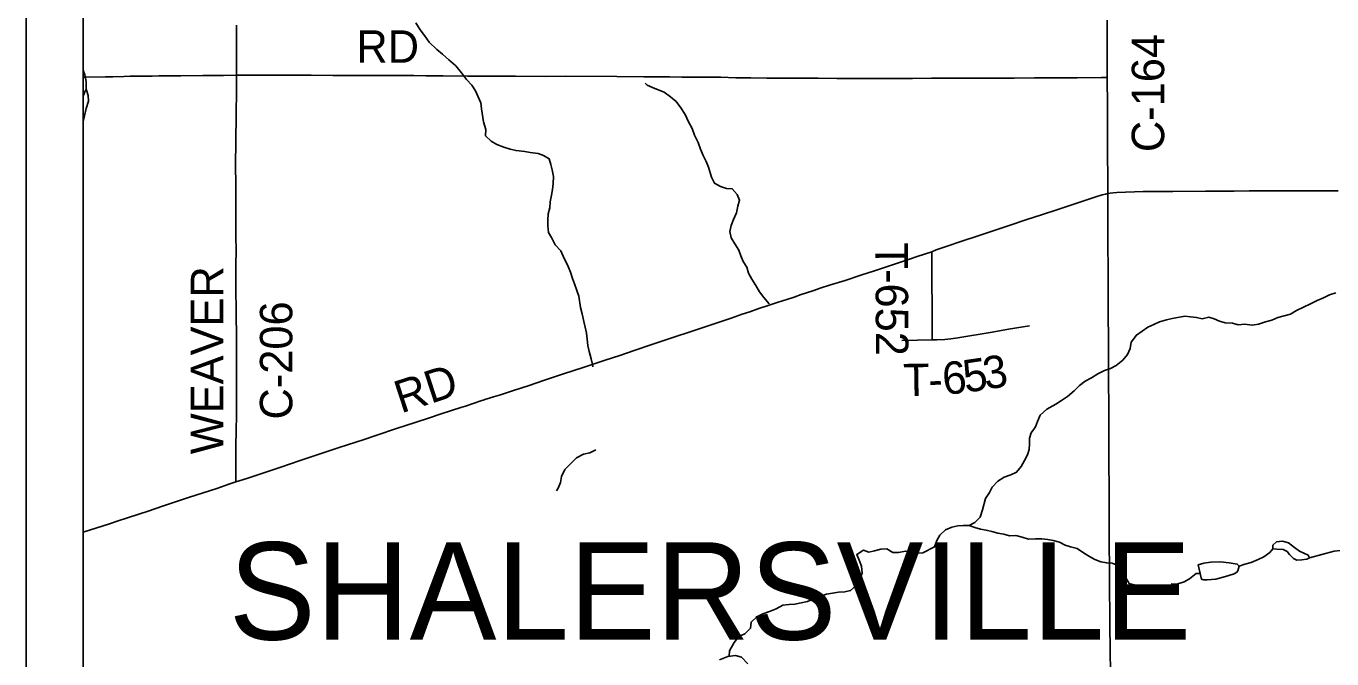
# Model space of a CAD drawing. Extents: x 0 to 34, y 0 to 22.
# Drawn here: x 13.344 to 15.63, y 16.128 to 17.236 of the extents above; entities that cross this region are included whole.
import ezdxf

# ---------------------------------------------------------------- set-up
doc = ezdxf.new("R2010")
doc.units = 0
for name, color, linetype in [('GM_X_Corporation', 7, 'Continuous'), ('GM_X_County_Road', 7, 'Continuous'), ('GM_X_County_Road_Text', 7, 'Continuous'), ('GM_X_Minor_Lake', 7, 'Continuous'), ('GM_X_Minor_River', 7, 'Continuous'), ('GM_X_Township_Road', 7, 'Continuous'), ('GM_X_Township_Road_Text', 7, 'Continuous'), ('GM_X_Township_Text', 7, 'Continuous'), ('SH_Data', 7, 'Continuous')]:
    doc.layers.add(name, color=color, linetype=linetype)

msp = doc.modelspace()

# ---------------------------------------------------------------- linework, layer by layer
at = {"layer": 'GM_X_Corporation'}
msp.add_lwpolyline([(13.4438, 19.9239), (13.4438, 15.6034)], dxfattribs=at)
at = {"layer": 'GM_X_County_Road'}
for points in [[(15.2371, 17.146), (15.2369, 17.1831), (15.2368, 17.2268), (15.2367, 17.2467)], [(13.7121, 17.1501), (13.7121, 17.1537), (13.7121, 17.1637), (13.7123, 17.1947), (13.7125, 17.2376)], [(13.7108, 16.4376), (13.7109, 16.4494), (13.7113, 16.4985), (13.7119, 16.5295), (13.712, 16.5531), (13.7121, 16.5867), (13.7122, 16.6003), (13.7122, 16.6432), (13.7123, 16.6693), (13.7121, 16.6911), (13.7118, 16.7327), (13.7117, 16.7427), (13.7113, 16.7706), (13.7111, 16.7861), (13.7111, 16.814), (13.7116, 16.8469), (13.7113, 16.8636), (13.7113, 16.8841), (13.7113, 16.9021), (13.711, 16.9208), (13.7108, 16.9413), (13.7108, 16.9674), (13.7106, 16.9829), (13.7103, 16.9985), (13.7108, 17.0283), (13.711, 17.0345), (13.7113, 17.0457), (13.7116, 17.0687), (13.7118, 17.0823), (13.7124, 17.1221), (13.7124, 17.1277), (13.7122, 17.1488), (13.7121, 17.1501)], [(15.238, 16.9428), (15.2378, 16.9671), (15.2376, 17.0151), (15.2375, 17.0511), (15.2372, 17.1087), (15.2371, 17.1324), (15.2371, 17.146)], [(15.238, 16.9428), (15.2422, 16.9436), (15.2476, 16.9443), (15.254, 16.9448), (15.2996, 16.9462), (15.3281, 16.9464), (15.3518, 16.9465), (15.409, 16.9467), (15.4593, 16.9472), (15.4854, 16.9474), (15.5252, 16.9474), (15.5674, 16.9475), (15.5985, 16.9474), (15.6289, 16.9476), (15.6413, 16.9475)], [(14.9296, 16.841), (14.9373, 16.844), (14.9532, 16.8494), (14.9843, 16.86), (15.0076, 16.8677), (15.0321, 16.8758), (15.0654, 16.8868), (15.0961, 16.8971), (15.1221, 16.9057), (15.1504, 16.9148), (15.1906, 16.9281), (15.2172, 16.937), (15.2281, 16.9404), (15.234, 16.9419), (15.238, 16.9428)], [(15.2425, 16.0936), (15.242, 16.153), (15.2417, 16.178), (15.2414, 16.2111), (15.2411, 16.2441), (15.2409, 16.2623), (15.2407, 16.2961), (15.2405, 16.3205), (15.2403, 16.3509), (15.2401, 16.3842), (15.2401, 16.4113), (15.2399, 16.4863), (15.2398, 16.5137), (15.2397, 16.5681), (15.2394, 16.6161), (15.2392, 16.6486), (15.239, 16.684), (15.2388, 16.7336), (15.2386, 16.7615), (15.2384, 16.7975), (15.2383, 16.8208), (15.2382, 16.8431), (15.2381, 16.8741), (15.238, 16.918), (15.238, 16.9428)], [(13.7108, 16.4376), (13.7305, 16.4439), (13.79, 16.4638), (13.8236, 16.4752), (13.892, 16.498), (13.9357, 16.5123), (13.9563, 16.5193), (13.994, 16.5319), (14.0052, 16.5356), (14.0283, 16.543), (14.0484, 16.5495), (14.0708, 16.5568), (14.1051, 16.5681), (14.1134, 16.5707), (14.1403, 16.5796), (14.1421, 16.5802), (14.1444, 16.581), (14.1491, 16.5825), (14.155, 16.5844), (14.1567, 16.5849), (14.1625, 16.5866), (14.1743, 16.5904), (14.1973, 16.5979), (14.2245, 16.6069), (14.2498, 16.6152), (14.2828, 16.6262), (14.3028, 16.6328), (14.3193, 16.6383), (14.3388, 16.6445), (14.3577, 16.6507), (14.3837, 16.6594), (14.4083, 16.6677), (14.4395, 16.6783), (14.466, 16.6872), (14.519, 16.7048), (14.5786, 16.7247), (14.5974, 16.7313), (14.6109, 16.7359), (14.6267, 16.7413), (14.6432, 16.7468), (14.661, 16.7525), (14.6758, 16.7573), (14.6888, 16.7615), (14.701, 16.7659), (14.7217, 16.7727), (14.7363, 16.7777), (14.7505, 16.7822), (14.7779, 16.7906), (14.8056, 16.7999), (14.8292, 16.8076), (14.8716, 16.8216), (14.8905, 16.8278), (14.904, 16.8325), (14.9296, 16.841)], [(13.4438, 16.3495), (13.4565, 16.3537), (13.4879, 16.3637), (13.5049, 16.3696), (13.5575, 16.3867), (13.5829, 16.3953), (13.6283, 16.4104), (13.678, 16.4264), (13.7003, 16.4342), (13.7108, 16.4376)]]:
    msp.add_lwpolyline(points, dxfattribs=at)
at = {"layer": 'GM_X_Minor_Lake'}
for p, q in [((15.545, 16.3191), (15.5519, 16.3161)), ((15.3961, 16.2925), (15.4012, 16.2698))]:
    msp.add_line(p, q, dxfattribs=at)
for points in [[(13.4438, 17.0702), (13.4462, 17.0791), (13.4491, 17.092), (13.4528, 17.1045), (13.4527, 17.1148), (13.4492, 17.1257), (13.4459, 17.1196), (13.4438, 17.1133)], [(15.5519, 16.3161), (15.5561, 16.3108), (15.5629, 16.3037), (15.569, 16.3007), (15.5777, 16.3011), (15.5864, 16.3027), (15.5909, 16.3046), (15.589, 16.3092), (15.5734, 16.3166), (15.5647, 16.323), (15.5544, 16.3313), (15.5438, 16.3342), (15.5336, 16.3326), (15.5268, 16.3269), (15.5269, 16.3205), (15.534, 16.3197), (15.545, 16.3191)], [(15.4012, 16.2698), (15.4027, 16.2668), (15.4054, 16.2664), (15.4122, 16.2665), (15.427, 16.2673), (15.4402, 16.2709), (15.4496, 16.2736), (15.4591, 16.2767), (15.464, 16.2794), (15.4658, 16.2821), (15.468, 16.2904), (15.4646, 16.2938), (15.4506, 16.296), (15.4351, 16.2978), (15.4184, 16.2972), (15.4063, 16.2956), (15.3961, 16.2925)], [(14.6076, 16.1189), (14.5965, 16.1309), (14.5863, 16.1339), (14.5723, 16.1319), (14.5579, 16.1261)]]:
    msp.add_lwpolyline(points, dxfattribs=at)
at = {"layer": 'GM_X_Minor_River'}
for points in [[(14.0263, 17.2417), (14.0339, 17.2296), (14.0412, 17.2198), (14.0496, 17.2077), (14.063, 17.1953), (14.0732, 17.187), (14.0843, 17.1769), (14.0965, 17.1664), (14.106, 17.1543), (14.1152, 17.1426), (14.1244, 17.1324), (14.1309, 17.1226), (14.1355, 17.112), (14.1401, 17.1018), (14.141, 17.0912), (14.1449, 17.0685), (14.1488, 17.0549), (14.1481, 17.0442), (14.1584, 17.0348), (14.1683, 17.0288), (14.1805, 17.024), (14.1915, 17.0203), (14.2017, 17.0181), (14.2169, 17.0163), (14.2267, 17.0149), (14.2404, 17.0127), (14.2498, 17.0094), (14.2597, 17.0037), (14.2628, 16.9939), (14.2652, 16.9841), (14.2675, 16.9727), (14.2669, 16.9606), (14.2658, 16.9499), (14.2636, 16.9397), (14.2614, 16.9283), (14.2608, 16.9177), (14.2582, 16.907), (14.2575, 16.896), (14.2572, 16.8861), (14.2588, 16.8748), (14.2646, 16.8646), (14.2704, 16.8529), (14.2799, 16.8427), (14.2861, 16.8291), (14.2914, 16.8193), (14.2968, 16.8053), (14.3007, 16.7943), (14.3038, 16.7845), (14.3084, 16.7728), (14.3115, 16.7629), (14.3147, 16.7432), (14.3178, 16.7319), (14.3206, 16.7186), (14.3229, 16.7088), (14.3249, 16.6982), (14.3265, 16.6875), (14.3273, 16.6769), (14.3297, 16.6663), (14.3332, 16.6535), (14.3356, 16.6432), (14.3363, 16.6391)], [(13.4492, 17.1257), (13.4491, 17.139), (13.4464, 17.1508), (13.4438, 17.1589)], [(14.6451, 16.7495), (14.6355, 16.7608), (14.6279, 16.7706), (14.6218, 16.7816), (14.6149, 16.7929), (14.6087, 16.8035), (14.6056, 16.8137), (14.5995, 16.8239), (14.5956, 16.8337), (14.5918, 16.8439), (14.5849, 16.8545), (14.5783, 16.8655), (14.576, 16.8764), (14.5786, 16.8871), (14.5823, 16.8974), (14.5875, 16.9088), (14.59, 16.9206), (14.5933, 16.9312), (14.5891, 16.9414), (14.5803, 16.9512), (14.5701, 16.9515), (14.5595, 16.9552), (14.5492, 16.9608), (14.5438, 16.9718), (14.5388, 16.9888), (14.5349, 16.999), (14.5292, 17.0096), (14.5249, 17.0206), (14.5207, 17.0323), (14.5141, 17.0448), (14.5103, 17.0565), (14.5037, 17.0686), (14.4976, 17.0814), (14.4903, 17.0927), (14.4819, 17.1041), (14.4724, 17.112), (14.4613, 17.1206), (14.4507, 17.1243), (14.4408, 17.1288), (14.4313, 17.1325), (14.4279, 17.1359)], [(15.4663, 16.7129), (15.478, 16.7138), (15.4909, 16.712), (15.5019, 16.7143), (15.5143, 16.7182), (15.5253, 16.7213), (15.5355, 16.7256), (15.5468, 16.7287), (15.5577, 16.7318), (15.5683, 16.738), (15.5807, 16.7438), (15.5928, 16.7499), (15.6045, 16.7557), (15.6154, 16.76), (15.6264, 16.7657), (15.6373, 16.7689)], [(14.5749, 16.1323), (14.5756, 16.1421), (14.5838, 16.1566), (14.5917, 16.1669), (14.6026, 16.1716), (14.6124, 16.1815), (14.6134, 16.1921), (14.6236, 16.2013), (14.6338, 16.2067), (14.6458, 16.2106), (14.6575, 16.2156), (14.6688, 16.2217), (14.6802, 16.2233), (14.69, 16.2238), (14.701, 16.2258), (14.7123, 16.2285), (14.7225, 16.2331), (14.7451, 16.2409), (14.7561, 16.2429), (14.7663, 16.2445), (14.7773, 16.2453), (14.7875, 16.2473), (14.7976, 16.2561), (14.804, 16.2679), (14.8081, 16.2778), (14.8068, 16.2899), (14.8026, 16.3005), (14.7983, 16.3107), (14.81, 16.3184), (14.8195, 16.3147), (14.8297, 16.317), (14.8403, 16.3198), (14.8509, 16.3206), (14.8615, 16.3142), (14.8714, 16.3143), (14.8835, 16.3167), (14.8937, 16.3145), (14.9032, 16.3127), (14.9141, 16.3135), (14.9345, 16.3239), (14.9386, 16.3349), (14.9438, 16.3445), (14.954, 16.3536), (14.9649, 16.3586), (14.9751, 16.3606), (14.9849, 16.3615), (14.9951, 16.3615), (15.0049, 16.3665), (15.0147, 16.3761), (15.0188, 16.3886), (15.0239, 16.4084), (15.0307, 16.4191), (15.0355, 16.4286), (15.0456, 16.4389), (15.0566, 16.4462), (15.0679, 16.4501), (15.0781, 16.4551), (15.0863, 16.465), (15.0919, 16.4753), (15.0971, 16.4852), (15.1005, 16.4947), (15.1008, 16.5046), (15.1011, 16.5141), (15.104, 16.5239), (15.1111, 16.5342), (15.1149, 16.5437), (15.1193, 16.5544), (15.131, 16.5651), (15.1468, 16.574), (15.1566, 16.5805), (15.1675, 16.5874), (15.1792, 16.597), (15.1886, 16.6065), (15.1983, 16.6142), (15.2093, 16.6203), (15.2206, 16.6269), (15.2319, 16.633), (15.2424, 16.6365), (15.2526, 16.6415), (15.2643, 16.6511), (15.2722, 16.661), (15.277, 16.6717), (15.2788, 16.6823), (15.2882, 16.6949), (15.298, 16.7018), (15.3081, 16.7087), (15.3183, 16.7137), (15.3285, 16.718), (15.3406, 16.7218), (15.3504, 16.7238), (15.3633, 16.7262), (15.3731, 16.7282), (15.3829, 16.7271), (15.3935, 16.7257), (15.4034, 16.7235), (15.4147, 16.7262), (15.4242, 16.7236), (15.4337, 16.7195), (15.4436, 16.7166), (15.4561, 16.7155), (15.4663, 16.7129)], [(14.3416, 16.4938), (14.3311, 16.4888), (14.3201, 16.4861), (14.3073, 16.4799), (14.287, 16.4593), (14.2814, 16.4475), (14.2796, 16.4369), (14.2752, 16.4266), (14.2725, 16.4224)], [(15.5909, 16.3046), (15.6344, 16.3163), (15.6453, 16.3179), (15.6563, 16.3169), (15.6666, 16.3147), (15.6772, 16.3129), (15.6867, 16.3095), (15.6996, 16.3005), (15.7102, 16.298), (15.7204, 16.3003), (15.7328, 16.3084), (15.743, 16.3187), (15.7505, 16.3282), (15.7504, 16.3392), (15.7545, 16.3495), (15.757, 16.3594), (15.7653, 16.3689), (15.7751, 16.3777), (15.786, 16.3831), (15.7922, 16.3831)], [(14.9951, 16.3615), (15.0054, 16.3578), (15.0149, 16.3549), (15.0247, 16.3534), (15.035, 16.3508), (15.0452, 16.3479), (15.0558, 16.3461), (15.0661, 16.3431), (15.0767, 16.3436), (15.088, 16.341), (15.099, 16.3373), (15.1111, 16.3378), (15.1225, 16.3378), (15.1327, 16.3368), (15.1422, 16.335), (15.1536, 16.332), (15.1635, 16.3268), (15.1729, 16.3242), (15.1843, 16.3209), (15.1954, 16.3138), (15.206, 16.307), (15.2155, 16.3018), (15.2258, 16.2977), (15.236, 16.2959), (15.2458, 16.2956), (15.2553, 16.2915), (15.2649, 16.2813), (15.2695, 16.2696), (15.2753, 16.2597), (15.2847, 16.2575), (15.2953, 16.2565), (15.3052, 16.2547), (15.3124, 16.2551)], [(15.468, 16.2904), (15.4779, 16.2939), (15.4888, 16.2966), (15.5013, 16.302), (15.5114, 16.3063), (15.5216, 16.314), (15.5269, 16.3205)], [(15.3491, 16.2592), (15.3589, 16.2589), (15.3714, 16.2627), (15.3812, 16.2681), (15.3924, 16.2773), (15.3995, 16.2774)]]:
    msp.add_lwpolyline(points, dxfattribs=at)
at = {"layer": 'GM_X_Township_Road'}
for points in [[(13.4438, 17.1465), (13.4488, 17.1466), (13.483, 17.1473), (13.4954, 17.1475), (13.5152, 17.1479), (13.5258, 17.1482), (13.5462, 17.1483), (13.5643, 17.1487), (13.5761, 17.149), (13.5966, 17.149), (13.6146, 17.1491), (13.6531, 17.1493), (13.6773, 17.1495), (13.6897, 17.1497), (13.7121, 17.1501)], [(13.7121, 17.1501), (13.7157, 17.1501), (13.7523, 17.1499), (13.7783, 17.1499), (13.7895, 17.1499), (13.8187, 17.1499), (13.8429, 17.1499), (13.8807, 17.1496), (13.8956, 17.1496), (13.9093, 17.1495), (13.931, 17.1496), (13.9571, 17.1494), (13.9894, 17.1494), (14.023, 17.1496), (14.0435, 17.1492), (14.0739, 17.1489), (14.1174, 17.1483), (14.1416, 17.1485), (14.1765, 17.1485), (14.2007, 17.1482), (14.2529, 17.148), (14.2883, 17.1483), (14.3785, 17.1479), (14.4257, 17.1474), (14.4705, 17.147), (14.4922, 17.1467), (14.5332, 17.1467), (14.5543, 17.1466), (14.5606, 17.1464), (14.5866, 17.1457), (14.6127, 17.1453), (14.6407, 17.1449), (14.667, 17.1448), (14.7002, 17.1449), (14.7306, 17.1448), (14.7636, 17.1445), (14.8009, 17.1442), (14.8319, 17.1444), (14.8631, 17.1444), (14.896, 17.1444), (14.9292, 17.1449), (14.9625, 17.145), (15.0073, 17.1449), (15.0432, 17.1452), (15.0741, 17.1449), (15.1098, 17.1454), (15.1415, 17.1454), (15.1546, 17.1454), (15.1657, 17.1454), (15.1843, 17.1453), (15.2268, 17.1459), (15.2371, 17.146)], [(14.9306, 16.6866), (14.9305, 16.6943), (14.9305, 16.6992), (14.9303, 16.7471), (14.9301, 16.785), (14.93, 16.8198), (14.9296, 16.841)], [(14.9306, 16.6866), (14.9388, 16.6868), (14.9525, 16.6872), (14.963, 16.6881), (14.9753, 16.69), (15.0354, 16.7002), (15.0642, 16.7052), (15.09, 16.7094), (15.101, 16.7112)], [(14.8773, 16.6856), (14.9046, 16.6863), (14.9306, 16.6866)]]:
    msp.add_lwpolyline(points, dxfattribs=at)
at = {"layer": 'SH_Data'}
for p, q in [((13.3438, 20.0239), (13.3438, 13.0239)), ((13.4438, 19.9239), (13.4438, 13.1239))]:
    msp.add_line(p, q, dxfattribs=at)

# ---------------------------------------------------------------- texts
at = {"layer": 'GM_X_County_Road_Text'}
for s, rotation, p in [('C-164', 90, (15.3367, 17.0154)), ('WEAVER', 90, (13.6889, 16.4862)), ('C-206', 90, (13.81, 16.547)), ('RD', 18.1207, (14.0002, 16.5574))]:
    msp.add_text(s, height=0.05682, rotation=rotation, dxfattribs=at).set_placement(p)
at = {"layer": 'GM_X_Township_Road_Text'}
for s, height, rotation, p in [('RD', 0.05682, 0, (13.9221, 17.1719)), ('T-652', 0.05682, 270.2823, (14.831, 16.8569)), ('6', 0.0568, 5.8438, (14.951, 16.59)), ('5', 0.0568, 8.2952, (14.9885, 16.5939)), ('3', 0.0568, 9.228, (15.0241, 16.5991)), ('T', 0.0568, 0.9858, (14.88, 16.5876)), ('-', 0.0568, 3.3098, (14.925, 16.5884))]:
    msp.add_text(s, height=height, rotation=rotation, dxfattribs=at).set_placement(p)
at = {"layer": 'GM_X_Township_Text'}
msp.add_text('SHALERSVILLE', height=0.170455, rotation=0, dxfattribs=at).set_placement((13.6988, 16.1615))

doc.saveas('drawing.dxf')
